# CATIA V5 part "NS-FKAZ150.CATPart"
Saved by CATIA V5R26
Part number: NS-FKAZ150
Bounding box of the stored display mesh (mm): x -99.1 to 99.1, y 0 to 198, z -49.9 to 49.9
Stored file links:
  R:\Document\坂尻\その他\ナベヤデータ変換\安全カバーキャスター\MCBKSAZ150\NS-FKAZ150.CATPart
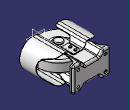
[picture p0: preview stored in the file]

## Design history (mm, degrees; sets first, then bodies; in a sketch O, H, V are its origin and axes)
Body1 (main body)
  Solid1: solid without history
